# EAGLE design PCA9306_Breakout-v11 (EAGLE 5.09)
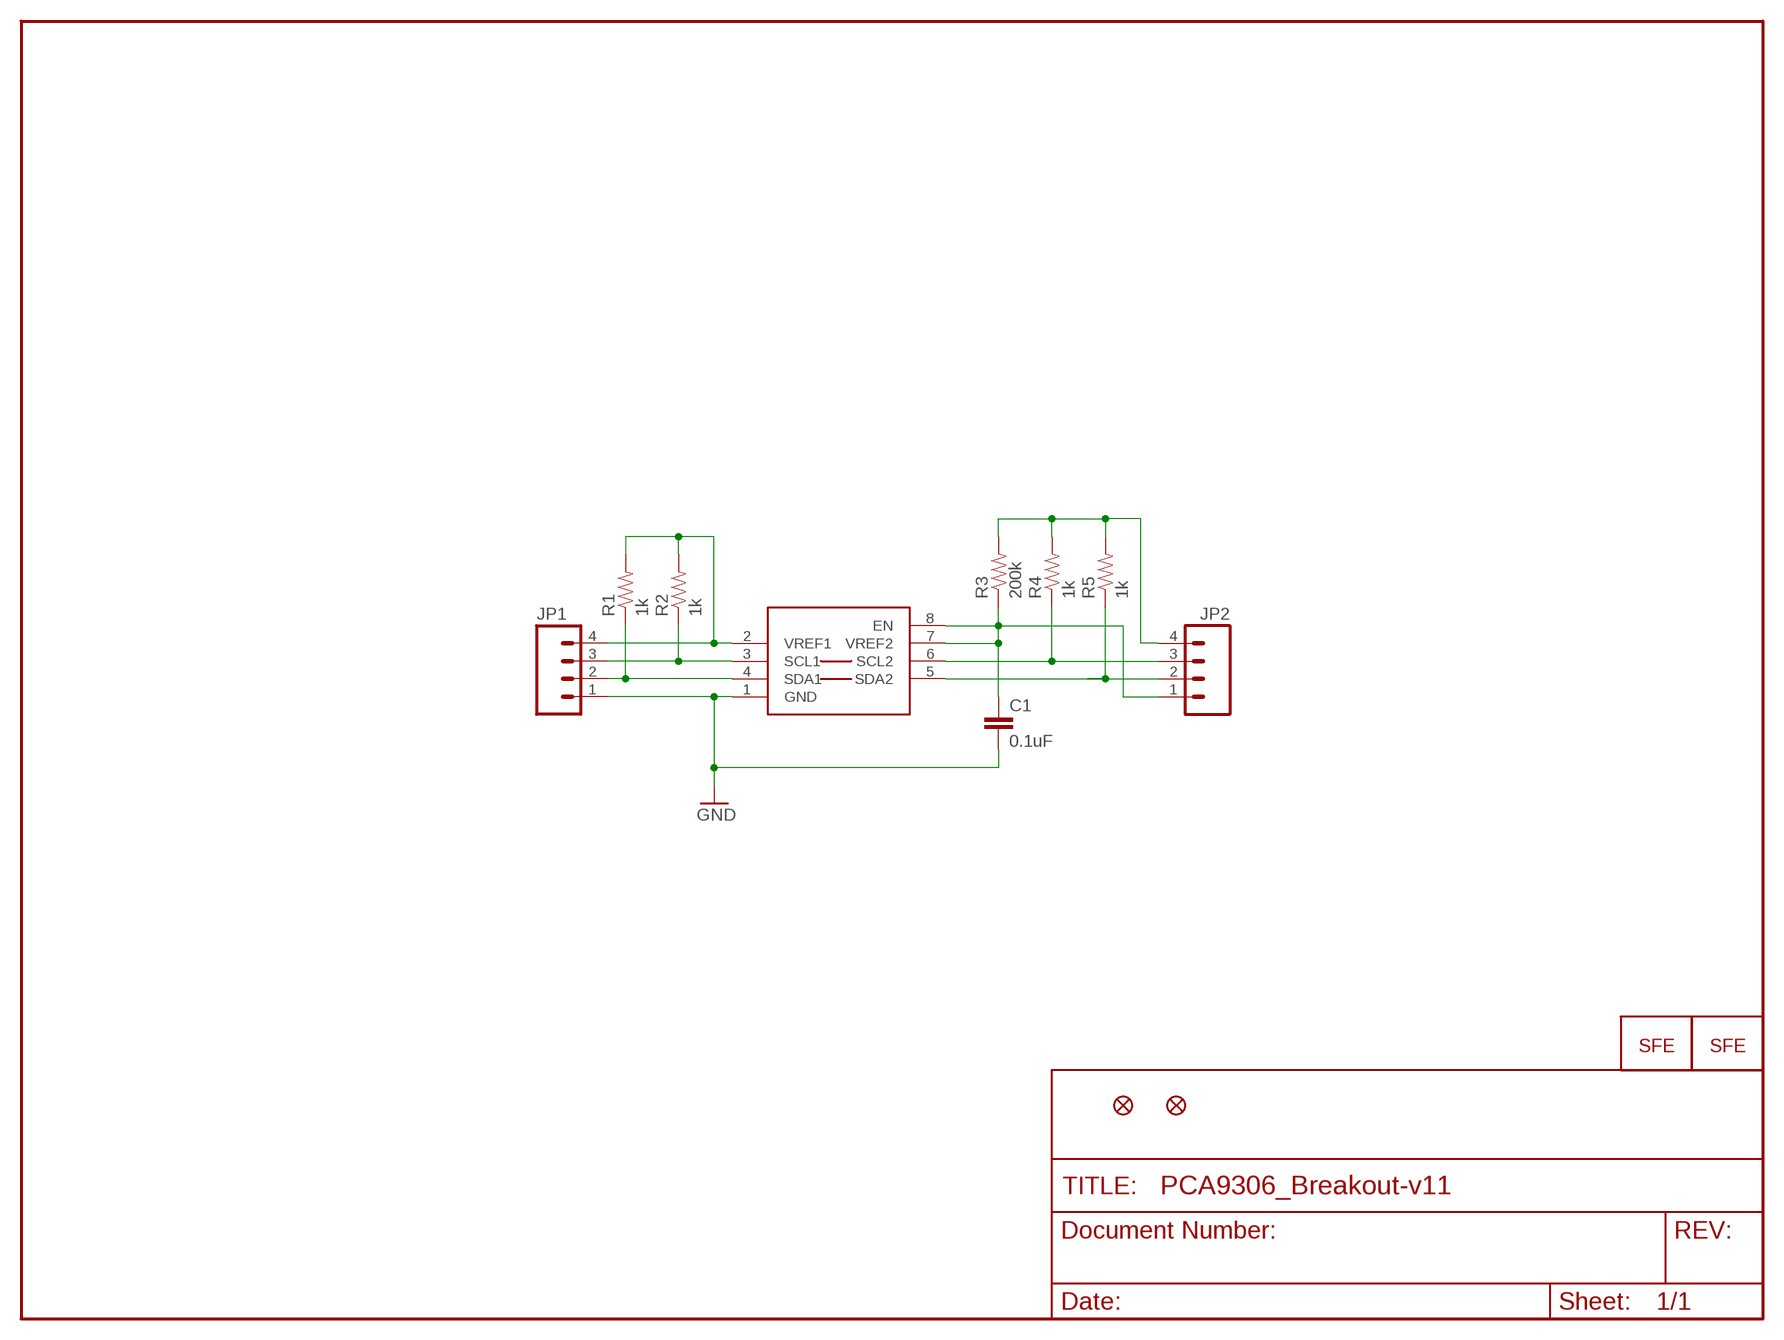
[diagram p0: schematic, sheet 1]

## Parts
C1  0.1uF  CAP0402-CAP  [0402-CAP]
JP1  M04PTH  [1X04]
JP2  M04PTH  [1X04]
JP3  LOGO-SFESK  [SFE-LOGO-FLAME]
JP4  LOGO-SFESK  [SFE-LOGO-FLAME]
JP5  FIDUCIAL1X2  [FIDUCIAL-1X2]
JP6  FIDUCIAL1X2  [FIDUCIAL-1X2]
R1  1k  RESISTOR0402-RES  [0402-RES]
R2  1k  RESISTOR0402-RES  [0402-RES]
R3  200k  RESISTOR0402-RES  [0402-RES]
R4  1k  RESISTOR0402-RES  [0402-RES]
R5  1k  RESISTOR0402-RES  [0402-RES]
U$1  PCA9306  [PSOP-8]

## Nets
GND: C1.2 JP1.1 U$1.1(GND)
N$1: JP2.4 R3.2 R4.2 R5.2
SCL1: JP1.3 R2.1 U$1.3(SCL1)
SCL2: JP2.3 R4.1 U$1.6(SCL2)
SDA1: JP1.2 R1.1 U$1.4(SDA1)
SDA2: JP2.2 R5.1 U$1.5(SDA2)
VREF1: JP1.4 R1.2 R2.2 U$1.2(VREF1)
VREF2: C1.1 JP2.1 R3.1 U$1.7(VREF2) U$1.8(EN)

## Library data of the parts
C1 = SparkFun:CAP: Capacitor
JP1 JP2 = SparkFun:M04: Header 4 Standard 4-pin 0.1" header. Use with straight break away headers (SKU : PRT-00116), right angle break away headers (PRT-00553), swiss pins (PRT-00743), machine pins (PRT-00117), and female headers (PRT-00115). Molex polarized connector foot print use with SKU : PRT-08231 with associated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
JP3 JP4 = SparkFun:LOGO-SFE: Spark Fun Electronics PCB Logo
JP5 JP6 = SparkFun:FIDUCIAL: Fiducial Alignment Points
R1-R5 = SparkFun:RESISTOR: Resistor
U$1 = SparkFun:PCA9306

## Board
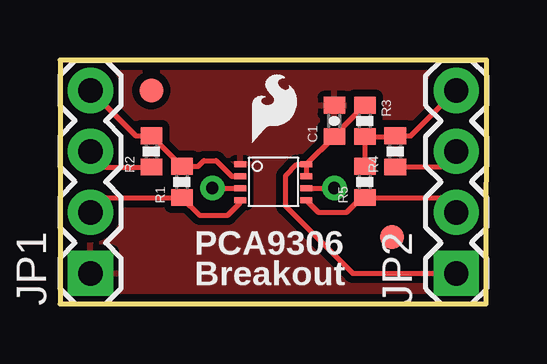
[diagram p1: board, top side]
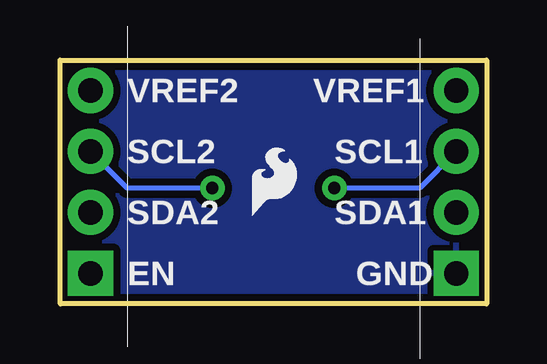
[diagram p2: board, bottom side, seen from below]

Size 17.78 x 10.16 mm. Coordinates in mm from the lower left corner, seen from the top.
Outline: 0,0 17.76,0 17.78,10.16 0,10.16 0,0
Copper layers (1*16): Top 0.035mm / dielectric 1.5mm / Bottom 0.035mm
Design rules "SparkFun": minimum track width 8mil, minimum drill 20mil, track to track 8mil, track to pad 8mil, pad to pad 8mil, via to via 8mil, smd to smd 8mil, copper to edge 8mil, drill to drill 8mil, minimum pad ring 12mil, minimum via ring 10mil, stop-mask expansion 4mil, vias tented up to drill 20mil, thermal gap 10mil

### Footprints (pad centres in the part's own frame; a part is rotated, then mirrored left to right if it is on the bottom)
0402-CAP = smd 0.7 x 0.9: 1 -0.65,0; 2 0.65,0
1X04 = drill 1.016 pad 1.88 square: 1 0,0 | drill 1.016 pad 1.88 round: 2 2.54,0; 3 5.08,0; 4 7.62,0
FIDUCIAL-1X2 = smd 1 x 1: 1 0,0
0402-RES = smd 0.7 x 0.9: 1 -0.65,0; 2 0.65,0
PSOP-8 = smd 0.25 x 0.5: 1 -0.73,-1.37; 2 -0.23,-1.37; 3 0.27,-1.37; 4 0.77,-1.37; 5 0.77,1.38; 6 0.27,1.38; 7 -0.23,1.38; 8 -0.73,1.38

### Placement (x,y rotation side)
C1  11.43,7.62 90 top
JP1  1.27,1.27 90 top
JP2  16.51,1.27 90 top
JP3  8,6.73 0 top
JP4  9.78,3.68 0 bottom
JP5  13.84,2.79 0 top
JP6  3.81,8.89 0 top
R1  5.08,5.08 90 top
R2  3.81,6.35 90 top
R3  12.7,7.62 270 top
R4  13.97,6.35 90 top
R5  12.7,5.08 90 top
U$1  8.89,5.08 270 top

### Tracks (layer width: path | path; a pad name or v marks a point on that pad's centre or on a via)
GND
  pour Bottom (isolate 0.305): 0,10.16 17.78,10.16 17.78,0 0,0
  pour Top (isolate 0.305): 0,10.16 17.78,10.16 17.78,0 0,0
N$1
  Top 0.203: JP2.4 14.62,7 R4.2 13.94,6.97 R3.2 R5.2
SCL1  (via drill 0.51)
  Top 0.203: R2.1 1.92,5.7 JP1.3 | U$1.3 6.37,4.81 v6.35,4.83
  Bottom 0.203: v6.35,4.83 2.79,4.83 JP1.3
SCL2  (via drill 0.51)
  Top 0.203: U$1.6 11.41,4.81 v11.43,4.83 | R4.1 15.86,5.7 JP2.3
  Bottom 0.203: v11.43,4.83 14.99,4.83 16.07,5.91 JP2.3
SDA1
  Top 0.203: JP1.2 1.89,4.43 R1.1 5.83,3.68 6.99,3.68 7.52,4.22 U$1.4
SDA2
  Top 0.203: 15.89,4.43 JP2.2 15.89,4.43 | U$1.5 10.77,3.81 11.94,3.81 12.44,4.31 12.58,4.31 R5.1 15.89,4.43
VREF1
  Top 0.203: JP1.4 3.16,7 R2.2 R1.2 5.75,5.73 5.99,5.97 6.5,5.97 6.93,5.54 7.16,5.31 U$1.2
VREF2
  Top 0.203: JP2.1 12.19,1.27 9.4,4.06 9.4,5.33 9.87,5.81 U$1.8 | U$1.8 U$1.7 | R3.1 11.43,7 C1.1 U$1.8

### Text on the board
tPlace: PCA9306 | Breakout
bPlace: VREF1 | VREF2 | SCL1 | SCL2 | SDA1 | SDA2 | GND | EN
